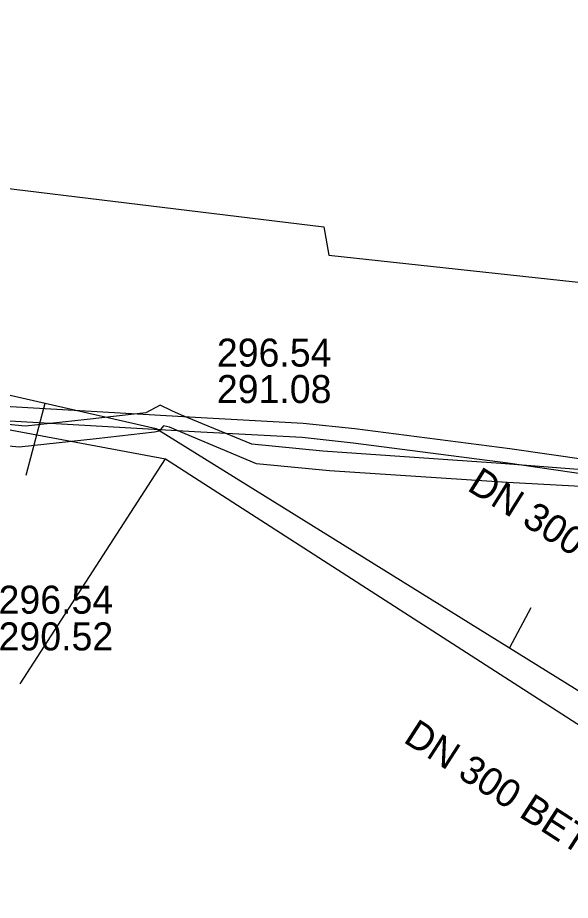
# Model space of a CAD drawing. Extents: x -595540 to -593988, y -1160850 to -1159202.
# Drawn here: x -594509.17 to -594493.39, y -1160116.79 to -1160091.58 of the extents above; entities that cross this region are included whole.
import ezdxf

# ---------------------------------------------------------------- set-up
doc = ezdxf.new("R2010")
doc.units = 0
for name, color, linetype in [('BVK-DESTOVA_popisy', 7, 'Continuous'), ('BVK-DESTOVA_trasa sítě', 7, 'Continuous'), ('BVK-SPLASKOVA_popisy', 7, 'Continuous'), ('BVK-SPLASKOVA_trasa sítě', 7, 'Continuous'), ('DESTOVA_trasa neprovozované sítě', 7, 'Continuous'), ('EON-NN_kabel', 7, 'Continuous'), ('EON-VN_kabel', 7, 'Continuous'), ('SPLASKOVA_neprovozovaná  trasa sítě', 7, 'Continuous'), ('TSB_kabel VO', 7, 'Continuous')]:
    doc.layers.add(name, color=color, linetype=linetype)

msp = doc.modelspace()

# ---------------------------------------------------------------- linework, layer by layer
at = {"layer": 'BVK-DESTOVA_trasa sítě'}
for p, q in [((-594551.1, -1160095.594), (-594504.942, -1160104.175)), ((-594504.942, -1160104.175), (-594477.1, -1160122.116))]:
    msp.add_line(p, q, dxfattribs=at)
at = {"layer": 'BVK-SPLASKOVA_popisy'}
msp.add_line((-594503.477, -1160100.745), (-594503.477, -1160100.745), dxfattribs=at)
at = {"layer": 'BVK-SPLASKOVA_trasa sítě'}
for points in [[(-594515.13, -1160101.05), (-594511.353, -1160101.911), (-594508.379, -1160102.589), (-594505.207, -1160103.312)], [(-594505.207, -1160103.312), (-594495.122, -1160109.574), (-594477.888, -1160120.275)]]:
    msp.add_lwpolyline(points, dxfattribs=at)
at = {"layer": 'DESTOVA_trasa neprovozované sítě'}
msp.add_line((-594509.096, -1160110.604), (-594504.942, -1160104.175), dxfattribs=at)
at = {"layer": 'EON-NN_kabel'}
for points in [[(-594474.64, -1160094.58), (-594477.644, -1160094.219), (-594478.83, -1160098.26), (-594480.743, -1160099.841), (-594482.282, -1160101.308), (-594482.804, -1160101.804), (-594484.755, -1160103.022), (-594485.333, -1160103.383), (-594486.769, -1160103.727), (-594487.452, -1160103.889), (-594490.214, -1160104.064), (-594492.871, -1160104.22), (-594495.114, -1160103.897), (-594499.535, -1160103.324), (-594501.012, -1160103.166), (-594504.098, -1160102.999), (-594510.039, -1160102.656)], [(-594510.061, -1160103.056), (-594504.12, -1160103.399), (-594501.044, -1160103.564), (-594499.583, -1160103.722), (-594495.168, -1160104.293), (-594492.889, -1160104.622), (-594490.19, -1160104.464), (-594487.392, -1160104.287), (-594486.677, -1160104.117), (-594485.177, -1160103.757), (-594484.543, -1160103.362), (-594482.558, -1160102.122), (-594482.006, -1160101.598), (-594480.471, -1160100.135), (-594478.408, -1160098.507), (-594477.256, -1160094.668), (-594474.689, -1160094.978)]]:
    msp.add_lwpolyline(points, dxfattribs=at)
at = {"layer": 'EON-VN_kabel'}
for points in [[(-594489.768, -1160105.148), (-594495.191, -1160104.858), (-594500.266, -1160104.521), (-594502.346, -1160104.321), (-594504.379, -1160103.464), (-594504.833, -1160103.271), (-594505.005, -1160103.237), (-594505.125, -1160103.392), (-594505.257, -1160103.415), (-594506.921, -1160103.604), (-594509.126, -1160103.842), (-594517.268, -1160103.056), (-594529.3, -1160101.606), (-594536.167, -1160100.901), (-594545.466, -1160099.961), (-594549.609, -1160099.505), (-594553.148, -1160099.22), (-594557.567, -1160098.416), (-594558.006, -1160098.261), (-594558.304, -1160097.987), (-594558.826, -1160097.313), (-594558.919, -1160096.532), (-594558.72, -1160095.429), (-594557.798, -1160091.58)], [(-594489.732, -1160104.75), (-594495.373, -1160104.308), (-594500.454, -1160103.964), (-594502.484, -1160103.763), (-594504.488, -1160102.933), (-594504.764, -1160102.803), (-594505.095, -1160102.643), (-594505.503, -1160102.869), (-594507.176, -1160103.059), (-594508.941, -1160103.243), (-594517.351, -1160102.446), (-594529.466, -1160101.016), (-594536.26, -1160100.347), (-594545.832, -1160099.39), (-594549.741, -1160098.943), (-594553.247, -1160098.603), (-594557.644, -1160097.647), (-594557.906, -1160097.584), (-594558.053, -1160097.325), (-594557.958, -1160096.877), (-594557.764, -1160095.256), (-594556.876, -1160091.677)]]:
    msp.add_lwpolyline(points, dxfattribs=at)
at = {"layer": 'SPLASKOVA_neprovozovaná  trasa sítě'}
for p, q in [((-594508.924, -1160104.649), (-594508.379, -1160102.589)), ((-594494.512, -1160108.432), (-594495.122, -1160109.574))]:
    msp.add_line(p, q, dxfattribs=at)
at = {"layer": 'TSB_kabel VO'}
msp.add_lwpolyline([(-594515.609, -1160095.708), (-594500.424, -1160097.558), (-594500.285, -1160098.358), (-594479.621, -1160100.597)], dxfattribs=at)

# ---------------------------------------------------------------- texts
at = {"layer": 'BVK-DESTOVA_popisy'}
for s, p in [('296.54', (-594509.709, -1160108.599)), ('290.52', (-594509.709, -1160109.649))]:
    msp.add_text(s, height=0.8, dxfattribs=at).set_placement(p)
msp.add_text('DN 300 BET', height=0.8, rotation=327.2094, dxfattribs=at).set_placement((-594498.185, -1160112.249))
at = {"layer": 'BVK-SPLASKOVA_popisy'}
for s, p in [('296.54', (-594503.477, -1160101.545)), ('291.08', (-594503.477, -1160102.585))]:
    msp.add_text(s, height=0.8, dxfattribs=at).set_placement(p)
msp.add_text('DN 300 KAM', height=0.8, rotation=327.9108, dxfattribs=at).set_placement((-594496.363, -1160105.058))

doc.saveas('drawing.dxf')
